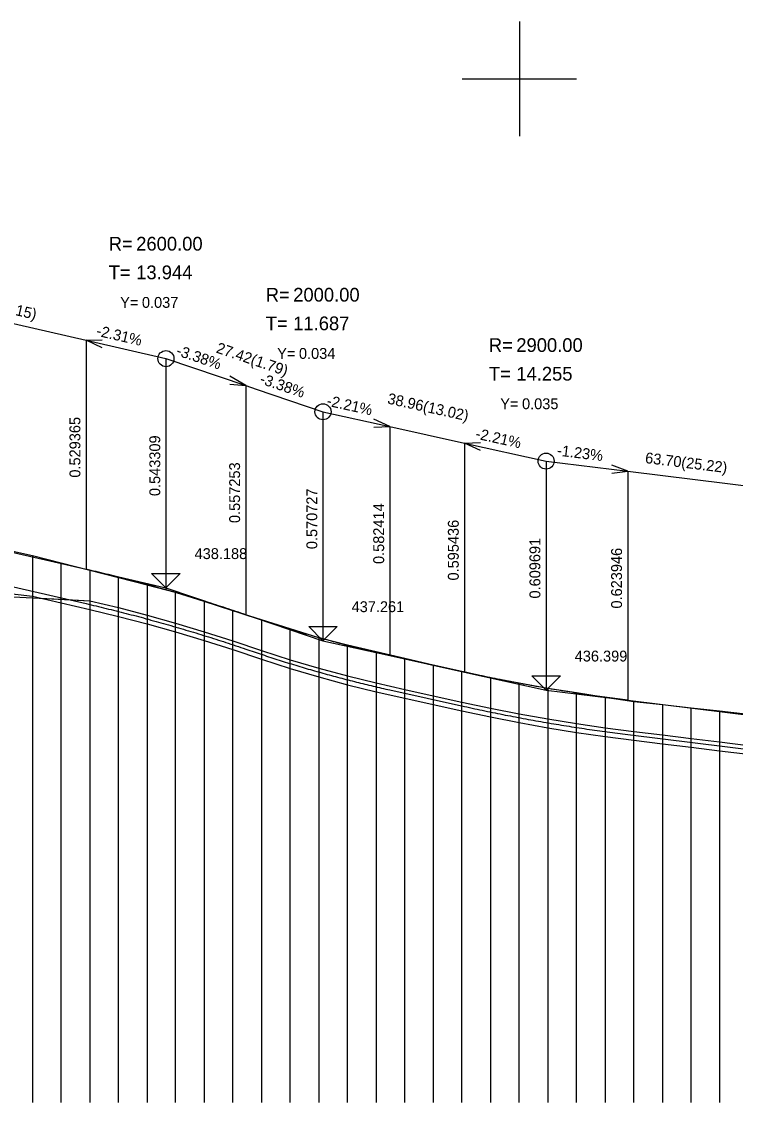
# Model space of a CAD drawing. Extents: x -240 to 1040, y 276 to 593.
# Drawn here: x 523.1 to 647.7, y 404 to 592.7 of the extents above; entities that cross this region are included whole.
import ezdxf

# ---------------------------------------------------------------- set-up
doc = ezdxf.new("R2010")
doc.units = 0
for name, color, linetype in [('1', 7, 'Continuous'), ('2', 7, 'Continuous'), ('FORMATY', 7, 'Continuous')]:
    doc.layers.add(name, color=color, linetype=linetype)

msp = doc.modelspace()

# ---------------------------------------------------------------- linework, layer by layer
at = {"layer": '1'}
for p, q in [((525, 499.46), (520, 500.56)), ((525, 499.46), (525, 404)), ((530, 498.16), (525, 499.46)), ((530, 404), (530, 498.16)), ((535, 496.86), (530, 498.16)), ((535, 496.86), (535, 404)), ((540, 495.6), (535, 496.86)), ((540, 404), (540, 495.6)), ((545, 494.33), (540, 495.6)), ((545, 494.33), (545, 404)), ((550, 493.05), (545, 494.33)), ((550, 404), (550, 493.05)), ((555, 491.46), (550, 493.05)), ((555, 491.46), (555, 404)), ((560, 489.86), (555, 491.46)), ((560, 404), (560, 489.86)), ((565, 488.28), (560, 489.86)), ((565, 488.28), (565, 404)), ((570, 486.71), (565, 488.28)), ((570, 404), (570, 486.71)), ((575, 485.13), (570, 486.71)), ((575, 485.13), (575, 404)), ((580, 483.87), (575, 485.13)), ((580, 404), (580, 483.87)), ((585, 482.7), (580, 483.87)), ((585, 482.7), (585, 404)), ((590, 481.51), (585, 482.7)), ((590, 404), (590, 481.51)), ((595, 480.37), (590, 481.51)), ((595, 480.37), (595, 404)), ((600, 479.23), (595, 480.37)), ((600, 404), (600, 479.23)), ((605, 478.13), (600, 479.23)), ((605, 478.13), (605, 404)), ((610, 477.19), (605, 478.13)), ((610, 404), (610, 477.19)), ((615, 476.28), (610, 477.19)), ((615, 476.28), (615, 404)), ((620, 475.5), (615, 476.28)), ((620, 404), (620, 475.5)), ((625, 474.72), (620, 475.5)), ((625, 474.72), (625, 404)), ((630, 473.97), (625, 474.72)), ((630, 404), (630, 473.97)), ((635, 473.42), (630, 473.97)), ((635, 473.42), (635, 404)), ((640, 472.87), (635, 473.42)), ((640, 404), (640, 472.87)), ((645, 472.31), (640, 472.87)), ((645, 472.31), (645, 404)), ((650, 471.76), (645, 472.31))]:
    msp.add_line(p, q, dxfattribs=at)
at = {"layer": '2'}
for p, q in [((507.22, 543.37), (534.36, 537.1)), ((534.36, 537.1), (537.16, 537.15)), ((534.36, 537.1), (534.36, 497.1)), ((537.16, 535.75), (534.36, 537.1)), ((534.36, 537.1), (548.31, 533.88)), ((548.31, 533.88), (548.31, 493.51)), ((548.31, 533.88), (562.25, 529.17)), ((562.25, 529.17), (559.45, 530.81)), ((559.45, 529.41), (562.25, 529.17)), ((562.25, 529.17), (562.25, 489.17)), ((562.25, 529.17), (564.04, 528.56)), ((564.04, 528.56), (575.73, 524.61)), ((575.73, 524.61), (575.73, 484.61)), ((575.73, 524.61), (587.41, 522.02)), ((587.41, 522.02), (584.61, 523.34)), ((584.61, 521.94), (587.41, 522.02)), ((587.41, 522.02), (587.41, 482.02)), ((587.41, 522.02), (600.44, 519.14)), ((600.44, 519.14), (603.24, 519.22)), ((600.44, 519.14), (600.44, 479.14)), ((603.24, 517.82), (600.44, 519.14)), ((600.44, 519.14), (614.69, 515.99)), ((614.69, 515.99), (614.69, 475.99)), ((614.69, 515.99), (628.95, 514.24)), ((628.95, 514.24), (626.15, 515.28)), ((626.15, 513.88), (628.95, 514.24)), ((628.95, 514.24), (628.95, 474.24)), ((628.95, 514.24), (654.16, 511.14)), ((507.22, 503.37), (534.36, 497.1)), ((507.22, 497.37), (534.36, 491.1)), ((534.8, 497), (534.36, 497.1)), ((534.36, 497.1), (548.31, 493.88)), ((535.24, 496.9), (534.8, 497)), ((535.67, 496.79), (535.24, 496.9)), ((536.11, 496.69), (535.67, 496.79)), ((536.54, 496.59), (536.11, 496.69)), ((536.98, 496.48), (536.54, 496.59)), ((537.41, 496.38), (536.98, 496.48)), ((537.85, 496.27), (537.41, 496.38)), ((538.29, 496.16), (537.85, 496.27)), ((538.72, 496.06), (538.29, 496.16)), ((539.16, 495.95), (538.72, 496.06)), ((539.59, 495.84), (539.16, 495.95)), ((540.03, 495.73), (539.59, 495.84)), ((540.47, 495.62), (540.03, 495.73)), ((540.9, 495.51), (540.47, 495.62)), ((541.34, 495.4), (540.9, 495.51)), ((541.77, 495.28), (541.34, 495.4)), ((542.21, 495.17), (541.77, 495.28)), ((542.64, 495.06), (542.21, 495.17)), ((543.08, 494.94), (542.64, 495.06)), ((543.52, 494.83), (543.08, 494.94)), ((543.95, 494.71), (543.52, 494.83)), ((544.39, 494.59), (543.95, 494.71)), ((544.82, 494.47), (544.39, 494.59)), ((548.31, 493.88), (545.81, 496.38)), ((545.81, 496.38), (550.81, 496.38)), ((550.81, 496.38), (548.31, 493.88)), ((545.26, 494.36), (544.82, 494.47)), ((545.69, 494.24), (545.26, 494.36)), ((546.13, 494.12), (545.69, 494.24)), ((546.57, 494), (546.13, 494.12)), ((547, 493.87), (546.57, 494)), ((547.44, 493.75), (547, 493.87)), ((547.87, 493.63), (547.44, 493.75)), ((548.31, 493.51), (547.87, 493.63)), ((548.31, 493.88), (562.25, 489.17)), ((548.74, 493.38), (548.31, 493.51)), ((549.18, 493.26), (548.74, 493.38)), ((549.62, 493.13), (549.18, 493.26)), ((550.05, 493), (549.62, 493.13)), ((550.49, 492.88), (550.05, 493)), ((550.92, 492.75), (550.49, 492.88)), ((551.36, 492.62), (550.92, 492.75)), ((551.8, 492.49), (551.36, 492.62)), ((525, 492.4), (530, 491.25)), ((525, 492.1), (530, 491.85)), ((530, 491.85), (535, 491.6)), ((530, 491.25), (535, 490.09)), ((534.36, 491.1), (534.8, 491)), ((534.8, 491), (535.24, 490.9)), ((535, 491.6), (540, 490.41)), ((535.24, 490.9), (535.67, 490.79)), ((535.67, 490.79), (536.11, 490.69)), ((552.23, 492.36), (551.8, 492.49)), ((552.67, 492.23), (552.23, 492.36)), ((553.1, 492.1), (552.67, 492.23)), ((553.54, 491.97), (553.1, 492.1)), ((553.97, 491.83), (553.54, 491.97)), ((554.41, 491.7), (553.97, 491.83)), ((554.85, 491.56), (554.41, 491.7)), ((555.28, 491.43), (554.85, 491.56)), ((555.72, 491.29), (555.28, 491.43)), ((556.15, 491.16), (555.72, 491.29)), ((556.59, 491.02), (556.15, 491.16)), ((557.02, 490.88), (556.59, 491.02)), ((557.46, 490.74), (557.02, 490.88)), ((557.9, 490.6), (557.46, 490.74)), ((535, 490.09), (540, 488.88)), ((536.11, 490.69), (536.54, 490.59)), ((536.54, 490.59), (536.98, 490.48)), ((536.98, 490.48), (537.41, 490.38)), ((537.41, 490.38), (537.85, 490.27)), ((537.85, 490.27), (538.29, 490.16)), ((538.29, 490.16), (538.72, 490.06)), ((538.72, 490.06), (539.16, 489.95)), ((539.16, 489.95), (539.59, 489.84)), ((539.59, 489.84), (540.03, 489.73)), ((540, 490.41), (545, 489.1)), ((540, 488.88), (545, 487.57)), ((540.03, 489.73), (540.47, 489.62)), ((540.47, 489.62), (540.9, 489.51)), ((540.9, 489.51), (541.34, 489.4)), ((541.34, 489.4), (541.77, 489.28)), ((541.77, 489.28), (542.21, 489.17)), ((542.21, 489.17), (542.64, 489.06)), ((542.64, 489.06), (543.08, 488.94)), ((543.08, 488.94), (543.52, 488.83)), ((545, 489.1), (550, 487.69)), ((558.33, 490.46), (557.9, 490.6)), ((558.77, 490.32), (558.33, 490.46)), ((559.2, 490.18), (558.77, 490.32)), ((559.64, 490.04), (559.2, 490.18)), ((560.07, 489.89), (559.64, 490.04)), ((560.51, 489.75), (560.07, 489.89)), ((560.95, 489.6), (560.51, 489.75)), ((561.38, 489.46), (560.95, 489.6)), ((561.82, 489.31), (561.38, 489.46)), ((562.25, 489.17), (561.82, 489.31)), ((562.25, 489.17), (564.04, 488.56)), ((543.52, 488.83), (543.95, 488.71)), ((543.95, 488.71), (544.39, 488.59)), ((544.39, 488.59), (544.82, 488.47)), ((544.82, 488.47), (545.26, 488.36)), ((545, 487.57), (550, 486.16)), ((545.26, 488.36), (545.69, 488.24)), ((545.69, 488.24), (546.13, 488.12)), ((546.13, 488.12), (546.57, 488)), ((546.57, 488), (547, 487.87)), ((547, 487.87), (547.44, 487.75)), ((547.44, 487.75), (547.87, 487.63)), ((547.87, 487.63), (548.31, 487.51)), ((548.31, 487.51), (548.74, 487.38)), ((548.74, 487.38), (549.18, 487.26)), ((549.18, 487.26), (549.62, 487.13)), ((549.62, 487.13), (550.05, 487)), ((550, 487.69), (555, 486.19)), ((550.05, 487), (550.49, 486.88)), ((564.41, 488.44), (564.04, 488.56)), ((564.04, 488.56), (575.73, 484.61)), ((564.77, 488.32), (564.41, 488.44)), ((565.14, 488.19), (564.77, 488.32)), ((565.5, 488.07), (565.14, 488.19)), ((565.87, 487.95), (565.5, 488.07)), ((566.23, 487.83), (565.87, 487.95)), ((566.6, 487.71), (566.23, 487.83)), ((566.96, 487.59), (566.6, 487.71)), ((567.33, 487.48), (566.96, 487.59)), ((567.69, 487.36), (567.33, 487.48)), ((568.06, 487.24), (567.69, 487.36)), ((568.42, 487.13), (568.06, 487.24)), ((568.79, 487.01), (568.42, 487.13)), ((569.15, 486.9), (568.79, 487.01)), ((575.73, 484.61), (573.23, 487.11)), ((573.23, 487.11), (578.23, 487.11)), ((578.23, 487.11), (575.73, 484.61)), ((550, 486.16), (555, 484.66)), ((550.49, 486.88), (550.92, 486.75)), ((550.92, 486.75), (551.36, 486.62)), ((551.36, 486.62), (551.8, 486.49)), ((551.8, 486.49), (552.23, 486.36)), ((552.23, 486.36), (552.67, 486.23)), ((552.67, 486.23), (553.1, 486.1)), ((553.1, 486.1), (553.54, 485.97)), ((553.54, 485.97), (553.97, 485.83)), ((553.97, 485.83), (554.41, 485.7)), ((554.41, 485.7), (554.85, 485.56)), ((554.85, 485.56), (555.28, 485.43)), ((555, 486.19), (560, 484.59)), ((555.28, 485.43), (555.72, 485.29)), ((555.72, 485.29), (556.15, 485.16)), ((556.15, 485.16), (556.59, 485.02)), ((569.52, 486.78), (569.15, 486.9)), ((569.88, 486.67), (569.52, 486.78)), ((570.25, 486.56), (569.88, 486.67)), ((570.61, 486.45), (570.25, 486.56)), ((570.98, 486.34), (570.61, 486.45)), ((571.34, 486.23), (570.98, 486.34)), ((571.71, 486.12), (571.34, 486.23)), ((572.07, 486.01), (571.71, 486.12)), ((572.44, 485.9), (572.07, 486.01)), ((572.81, 485.79), (572.44, 485.9)), ((573.17, 485.68), (572.81, 485.79)), ((573.54, 485.58), (573.17, 485.68)), ((573.9, 485.47), (573.54, 485.58)), ((574.27, 485.37), (573.9, 485.47)), ((574.63, 485.26), (574.27, 485.37)), ((575, 485.16), (574.63, 485.26)), ((575.36, 485.05), (575, 485.16)), ((555, 484.66), (560, 483.06)), ((556.59, 485.02), (557.02, 484.88)), ((557.02, 484.88), (557.46, 484.74)), ((557.46, 484.74), (557.9, 484.6)), ((557.9, 484.6), (558.33, 484.46)), ((558.33, 484.46), (558.77, 484.32)), ((558.77, 484.32), (559.2, 484.18)), ((559.2, 484.18), (559.64, 484.04)), ((559.64, 484.04), (560.07, 483.89)), ((560, 484.59), (565, 482.91)), ((560.07, 483.89), (560.51, 483.75)), ((560.51, 483.75), (560.95, 483.6)), ((560.95, 483.6), (561.38, 483.46)), ((561.38, 483.46), (561.82, 483.31)), ((561.82, 483.31), (562.25, 483.17)), ((575.73, 484.95), (575.36, 485.05)), ((576.09, 484.85), (575.73, 484.95)), ((575.73, 484.61), (587.41, 482.02)), ((576.46, 484.75), (576.09, 484.85)), ((576.82, 484.65), (576.46, 484.75)), ((577.19, 484.55), (576.82, 484.65)), ((577.55, 484.45), (577.19, 484.55)), ((577.92, 484.35), (577.55, 484.45)), ((578.28, 484.25), (577.92, 484.35)), ((578.65, 484.16), (578.28, 484.25)), ((579.01, 484.06), (578.65, 484.16)), ((579.38, 483.96), (579.01, 484.06)), ((579.74, 483.87), (579.38, 483.96)), ((580.11, 483.77), (579.74, 483.87)), ((580.47, 483.68), (580.11, 483.77)), ((580.84, 483.59), (580.47, 483.68)), ((581.21, 483.49), (580.84, 483.59)), ((581.57, 483.4), (581.21, 483.49)), ((581.94, 483.31), (581.57, 483.4)), ((582.3, 483.22), (581.94, 483.31)), ((582.67, 483.13), (582.3, 483.22)), ((560, 483.06), (565, 481.38)), ((562.25, 483.17), (564.04, 482.56)), ((564.04, 482.56), (564.41, 482.44)), ((564.41, 482.44), (564.77, 482.32)), ((564.77, 482.32), (565.14, 482.19)), ((565, 482.91), (570, 481.31)), ((565, 481.38), (570, 479.78)), ((565.14, 482.19), (565.5, 482.07)), ((565.5, 482.07), (565.87, 481.95)), ((565.87, 481.95), (566.23, 481.83)), ((566.23, 481.83), (566.6, 481.71)), ((566.6, 481.71), (566.96, 481.59)), ((566.96, 481.59), (567.33, 481.48)), ((567.33, 481.48), (567.69, 481.36)), ((567.69, 481.36), (568.06, 481.24)), ((570, 481.31), (575, 479.83)), ((583.03, 483.04), (582.67, 483.13)), ((583.4, 482.95), (583.03, 483.04)), ((583.76, 482.87), (583.4, 482.95)), ((584.13, 482.78), (583.76, 482.87)), ((584.49, 482.69), (584.13, 482.78)), ((584.86, 482.61), (584.49, 482.69)), ((585.22, 482.52), (584.86, 482.61)), ((585.59, 482.44), (585.22, 482.52)), ((585.95, 482.35), (585.59, 482.44)), ((586.32, 482.27), (585.95, 482.35)), ((586.68, 482.19), (586.32, 482.27)), ((587.05, 482.11), (586.68, 482.19)), ((587.41, 482.02), (587.05, 482.11)), ((587.41, 482.02), (600.44, 479.14)), ((568.06, 481.24), (568.42, 481.13)), ((568.42, 481.13), (568.79, 481.01)), ((568.79, 481.01), (569.15, 480.9)), ((569.15, 480.9), (569.52, 480.78)), ((569.52, 480.78), (569.88, 480.67)), ((569.88, 480.67), (570.25, 480.56)), ((570, 479.78), (575, 478.3)), ((570.25, 480.56), (570.61, 480.45)), ((570.61, 480.45), (570.98, 480.34)), ((570.98, 480.34), (571.34, 480.23)), ((571.34, 480.23), (571.71, 480.12)), ((571.71, 480.12), (572.07, 480.01)), ((572.07, 480.01), (572.44, 479.9)), ((572.44, 479.9), (572.81, 479.79)), ((572.81, 479.79), (573.17, 479.68)), ((573.17, 479.68), (573.54, 479.58)), ((573.54, 479.58), (573.9, 479.47)), ((573.9, 479.47), (574.27, 479.37)), ((575, 479.83), (580, 478.48)), ((574.27, 479.37), (574.63, 479.26)), ((574.63, 479.26), (575, 479.16)), ((575, 479.16), (575.36, 479.05)), ((575, 478.3), (580, 476.94)), ((575.36, 479.05), (575.73, 478.95)), ((575.73, 478.95), (576.09, 478.85)), ((576.09, 478.85), (576.46, 478.75)), ((576.46, 478.75), (576.82, 478.65)), ((576.82, 478.65), (577.19, 478.55)), ((577.19, 478.55), (577.55, 478.45)), ((577.55, 478.45), (577.92, 478.35)), ((577.92, 478.35), (578.28, 478.25)), ((578.28, 478.25), (578.65, 478.16)), ((578.65, 478.16), (579.01, 478.06)), ((579.01, 478.06), (579.38, 477.96)), ((579.38, 477.96), (579.74, 477.87)), ((579.74, 477.87), (580.11, 477.77)), ((580, 478.48), (585, 477.25)), ((580.11, 477.77), (580.47, 477.68)), ((580.47, 477.68), (580.84, 477.59)), ((580.84, 477.59), (581.21, 477.49)), ((600.88, 479.05), (600.44, 479.14)), ((600.44, 479.14), (614.69, 475.99)), ((601.33, 478.95), (600.88, 479.05)), ((601.77, 478.85), (601.33, 478.95)), ((602.22, 478.75), (601.77, 478.85)), ((602.66, 478.66), (602.22, 478.75)), ((603.11, 478.56), (602.66, 478.66)), ((603.55, 478.47), (603.11, 478.56)), ((604, 478.38), (603.55, 478.47)), ((604.45, 478.28), (604, 478.38)), ((604.89, 478.19), (604.45, 478.28)), ((605.34, 478.1), (604.89, 478.19)), ((605.78, 478.01), (605.34, 478.1)), ((606.23, 477.92), (605.78, 478.01)), ((606.67, 477.83), (606.23, 477.92)), ((607.12, 477.74), (606.67, 477.83)), ((607.56, 477.65), (607.12, 477.74)), ((608.01, 477.57), (607.56, 477.65)), ((608.45, 477.48), (608.01, 477.57)), ((614.69, 475.99), (612.19, 478.49)), ((612.19, 478.49), (617.19, 478.49)), ((617.19, 478.49), (614.69, 475.99)), ((580, 476.94), (585, 475.71)), ((581.21, 477.49), (581.57, 477.4)), ((581.57, 477.4), (581.94, 477.31)), ((581.94, 477.31), (582.3, 477.22)), ((582.3, 477.22), (582.67, 477.13)), ((582.67, 477.13), (583.03, 477.04)), ((583.03, 477.04), (583.4, 476.95)), ((583.4, 476.95), (583.76, 476.87)), ((583.76, 476.87), (584.13, 476.78)), ((584.13, 476.78), (584.49, 476.69)), ((584.49, 476.69), (584.86, 476.61)), ((584.86, 476.61), (585.22, 476.52)), ((585, 477.25), (590, 476.13)), ((585, 475.71), (590, 474.59)), ((585.22, 476.52), (585.59, 476.44)), ((585.59, 476.44), (585.95, 476.35)), ((585.95, 476.35), (586.32, 476.27)), ((586.32, 476.27), (586.68, 476.19)), ((586.68, 476.19), (587.05, 476.11)), ((587.05, 476.11), (587.41, 476.02)), ((587.41, 476.02), (600.44, 473.14)), ((590, 476.13), (595, 475.02)), ((608.9, 477.39), (608.45, 477.48)), ((609.35, 477.31), (608.9, 477.39)), ((609.79, 477.22), (609.35, 477.31)), ((610.24, 477.14), (609.79, 477.22)), ((610.68, 477.06), (610.24, 477.14)), ((611.13, 476.98), (610.68, 477.06)), ((611.57, 476.89), (611.13, 476.98)), ((612.02, 476.81), (611.57, 476.89)), ((612.46, 476.73), (612.02, 476.81)), ((612.91, 476.65), (612.46, 476.73)), ((613.35, 476.57), (612.91, 476.65)), ((613.8, 476.5), (613.35, 476.57)), ((614.25, 476.42), (613.8, 476.5)), ((614.69, 476.34), (614.25, 476.42)), ((615.14, 476.26), (614.69, 476.34)), ((614.69, 475.99), (628.95, 474.24)), ((615.58, 476.19), (615.14, 476.26)), ((616.03, 476.11), (615.58, 476.19)), ((616.47, 476.04), (616.03, 476.11)), ((616.92, 475.97), (616.47, 476.04)), ((617.36, 475.89), (616.92, 475.97)), ((617.81, 475.82), (617.36, 475.89)), ((618.25, 475.75), (617.81, 475.82)), ((618.7, 475.68), (618.25, 475.75)), ((619.15, 475.61), (618.7, 475.68)), ((590, 474.59), (595, 473.49)), ((595, 475.02), (600, 473.91)), ((600, 473.91), (605, 472.84)), ((619.59, 475.54), (619.15, 475.61)), ((620.04, 475.47), (619.59, 475.54)), ((620.48, 475.4), (620.04, 475.47)), ((620.93, 475.33), (620.48, 475.4)), ((621.37, 475.27), (620.93, 475.33)), ((621.82, 475.2), (621.37, 475.27)), ((622.26, 475.14), (621.82, 475.2)), ((622.71, 475.07), (622.26, 475.14)), ((623.15, 475.01), (622.71, 475.07)), ((623.6, 474.94), (623.15, 475.01)), ((624.05, 474.88), (623.6, 474.94)), ((624.49, 474.82), (624.05, 474.88)), ((624.94, 474.76), (624.49, 474.82)), ((625.38, 474.7), (624.94, 474.76)), ((625.83, 474.64), (625.38, 474.7)), ((626.27, 474.58), (625.83, 474.64)), ((626.72, 474.52), (626.27, 474.58)), ((627.16, 474.46), (626.72, 474.52)), ((627.61, 474.41), (627.16, 474.46)), ((628.05, 474.35), (627.61, 474.41)), ((628.5, 474.29), (628.05, 474.35)), ((628.95, 474.24), (628.5, 474.29)), ((628.95, 474.24), (654.16, 471.14)), ((595, 473.49), (600, 472.38)), ((600, 472.38), (605, 471.31)), ((600.44, 473.14), (600.88, 473.05)), ((600.88, 473.05), (601.33, 472.95)), ((601.33, 472.95), (601.77, 472.85)), ((601.77, 472.85), (602.22, 472.75)), ((602.22, 472.75), (602.66, 472.66)), ((602.66, 472.66), (603.11, 472.56)), ((603.11, 472.56), (603.55, 472.47)), ((603.55, 472.47), (604, 472.38)), ((604, 472.38), (604.45, 472.28)), ((604.45, 472.28), (604.89, 472.19)), ((604.89, 472.19), (605.34, 472.1)), ((605, 472.84), (610, 471.86)), ((605.34, 472.1), (605.78, 472.01)), ((605.78, 472.01), (606.23, 471.92)), ((606.23, 471.92), (606.67, 471.83)), ((610, 471.86), (615, 470.96)), ((605, 471.31), (610, 470.33)), ((606.67, 471.83), (607.12, 471.74)), ((607.12, 471.74), (607.56, 471.65)), ((607.56, 471.65), (608.01, 471.57)), ((608.01, 471.57), (608.45, 471.48)), ((608.45, 471.48), (608.9, 471.39)), ((608.9, 471.39), (609.35, 471.31)), ((609.35, 471.31), (609.79, 471.22)), ((609.79, 471.22), (610.24, 471.14)), ((610, 470.33), (615, 469.43)), ((610.24, 471.14), (610.68, 471.06)), ((610.68, 471.06), (611.13, 470.98)), ((611.13, 470.98), (611.57, 470.89)), ((611.57, 470.89), (612.02, 470.81)), ((612.02, 470.81), (612.46, 470.73)), ((612.46, 470.73), (612.91, 470.65)), ((612.91, 470.65), (613.35, 470.57)), ((613.35, 470.57), (613.8, 470.5)), ((613.8, 470.5), (614.25, 470.42)), ((614.25, 470.42), (614.69, 470.34)), ((614.69, 470.34), (615.14, 470.26)), ((615, 470.96), (620, 470.15)), ((615.14, 470.26), (615.58, 470.19)), ((615.58, 470.19), (616.03, 470.11)), ((616.03, 470.11), (616.47, 470.04)), ((616.47, 470.04), (616.92, 469.97)), ((616.92, 469.97), (617.36, 469.89)), ((620, 470.15), (625, 469.42)), ((615, 469.43), (620, 468.62)), ((617.36, 469.89), (617.81, 469.82)), ((617.81, 469.82), (618.25, 469.75)), ((618.25, 469.75), (618.7, 469.68)), ((618.7, 469.68), (619.15, 469.61)), ((619.15, 469.61), (619.59, 469.54)), ((619.59, 469.54), (620.04, 469.47)), ((620, 468.62), (625, 467.89)), ((620.04, 469.47), (620.48, 469.4)), ((620.48, 469.4), (620.93, 469.33)), ((620.93, 469.33), (621.37, 469.27)), ((621.37, 469.27), (621.82, 469.2)), ((621.82, 469.2), (622.26, 469.14)), ((622.26, 469.14), (622.71, 469.07)), ((622.71, 469.07), (623.15, 469.01)), ((623.15, 469.01), (623.6, 468.94)), ((623.6, 468.94), (624.05, 468.88)), ((624.05, 468.88), (624.49, 468.82)), ((624.49, 468.82), (624.94, 468.76)), ((624.94, 468.76), (625.38, 468.7)), ((625, 469.42), (630, 468.78)), ((625.38, 468.7), (625.83, 468.64)), ((625.83, 468.64), (626.27, 468.58)), ((626.27, 468.58), (626.72, 468.52)), ((626.72, 468.52), (627.16, 468.46)), ((627.16, 468.46), (627.61, 468.41)), ((627.61, 468.41), (628.05, 468.35)), ((628.05, 468.35), (628.5, 468.29)), ((628.5, 468.29), (628.95, 468.24)), ((628.95, 468.24), (654.16, 465.14)), ((630, 468.78), (635, 468.17)), ((635, 468.17), (640, 467.55)), ((625, 467.89), (630, 467.25)), ((630, 467.25), (635, 466.63)), ((635, 466.63), (640, 466.02)), ((640, 467.55), (645, 466.94)), ((645, 466.94), (650, 466.32)), ((640, 466.02), (645, 465.41)), ((645, 465.41), (650, 464.79))]:
    msp.add_line(p, q, dxfattribs=at)
for points in [[(515, 492.61), (535, 491.6), (540, 490.41), (545, 489.1), (550, 487.69), (555, 486.19), (560, 484.59), (565, 482.91), (570, 481.31), (575, 479.83), (580, 478.48), (585, 477.25), (590, 476.13), (595, 475.02), (600, 473.91), (605, 472.84), (610, 471.86), (615, 470.96), (620, 470.15), (625, 469.42), (630, 468.78), (635, 468.17), (640, 467.55), (645, 466.94), (650, 466.32)], [(520, 493), (525, 492.4), (530, 491.25), (535, 490.09), (540, 488.88), (545, 487.57), (550, 486.16), (555, 484.66), (560, 483.06), (565, 481.38), (570, 479.78), (575, 478.3), (580, 476.94), (585, 475.71), (590, 474.59), (595, 473.49), (600, 472.38), (605, 471.31), (610, 470.33), (615, 469.43), (620, 468.62), (625, 467.89), (630, 467.25), (635, 466.63), (640, 466.02), (645, 465.41), (650, 464.79)]]:
    msp.add_lwpolyline(points, dxfattribs=at)
for centre in [(548.31, 533.88), (575.73, 524.61), (614.69, 515.99)]:
    msp.add_circle(centre, 1.4, dxfattribs=at)
at = {"layer": 'FORMATY'}
for p, q in [((610.02, 592.74), (610.02, 572.74)), ((610.02, 592.74), (610.02, 572.74)), ((610.02, 592.74), (610.02, 572.74)), ((610.02, 592.74), (610.02, 572.74)), ((610.02, 592.74), (610.02, 572.74)), ((610.02, 592.74), (610.02, 572.74)), ((600.02, 582.74), (620.02, 582.74)), ((600.02, 582.74), (620.02, 582.74)), ((600.02, 582.74), (620.02, 582.74)), ((600.02, 582.74), (620.02, 582.74)), ((600.02, 582.74), (620.02, 582.74)), ((600.02, 582.74), (620.02, 582.74))]:
    msp.add_line(p, q, dxfattribs=at)

# ---------------------------------------------------------------- texts
at = {"layer": '2'}
for s, height, p in [('R=', 2.4, (538.31, 552.75)), ('2600.00', 2.4, (543.11, 552.75)), ('T=', 2.4, (538.31, 547.75)), ('13.944', 2.4, (543.11, 547.75)), ('R=', 2.4, (565.73, 543.84)), ('2000.00', 2.4, (570.53, 543.84)), ('Y=', 1.9, (540.31, 542.75)), ('0.037', 1.9, (544.11, 542.75)), ('T=', 2.4, (565.73, 538.84)), ('11.687', 2.4, (570.53, 538.84)), ('R=', 2.4, (604.69, 535.05)), ('2900.00', 2.4, (609.49, 535.05)), ('Y=', 1.9, (567.73, 533.84)), ('0.034', 1.9, (571.53, 533.84)), ('T=', 2.4, (604.69, 530.05)), ('14.255', 2.4, (609.49, 530.05)), ('Y=', 1.9, (606.69, 525.05)), ('0.035', 1.9, (610.49, 525.05)), ('438.188', 1.9, (553.31, 498.88)), ('437.261', 1.9, (580.73, 489.61)), ('436.399', 1.9, (619.69, 480.99))]:
    msp.add_text(s, height=height, dxfattribs=at).set_placement(p)
for s, rotation, p in [('49.73(27.15)', 347.0018, (511.44, 543.91)), (' -2.31%', 347.0018, (535.34, 538.07)), ('27.42(1.79)', 341.3196, (556.93, 534.97)), (' -3.38%', 341.3196, (549.28, 534.75)), (' -3.38%', 341.3196, (563.88, 529.81)), (' -2.21%', 347.5254, (575.57, 525.84)), ('38.96(13.02)', 347.5254, (586.86, 526.06)), ('0.529365', 90, (533.36, 513.1)), (' -2.21%', 347.5254, (601.56, 520.09)), ('0.543309', 90, (547.31, 509.88)), (' -1.23%', 352.9923, (615.82, 517.05)), ('63.70(25.22)', 352.9923, (631.91, 515.66)), ('0.557253', 90, (561.25, 505.17)), ('0.570727', 90, (574.73, 500.61)), ('0.582414', 90, (586.41, 498.02)), ('0.595436', 90, (599.44, 495.14)), ('0.609691', 90, (613.69, 491.99)), ('0.623946', 90, (627.95, 490.24))]:
    msp.add_text(s, height=1.9, rotation=rotation, dxfattribs=at).set_placement(p)

doc.saveas('drawing.dxf')
